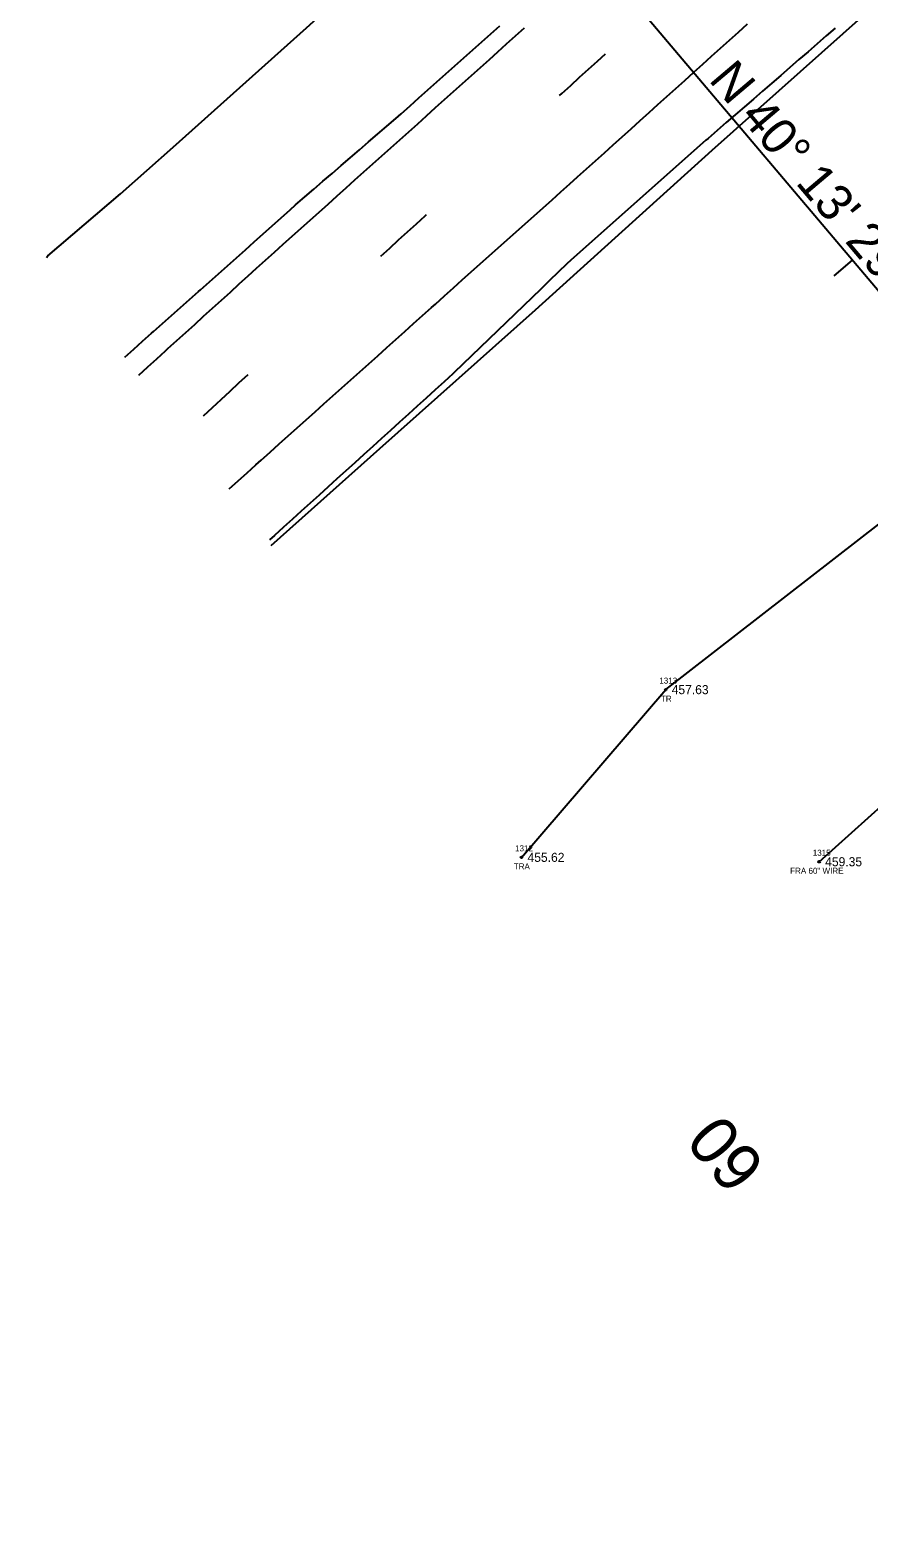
# Model space of a CAD drawing. Extents: x 1745838 to 1751416, y 649214 to 655806.
# Drawn here: x 1749097.1 to 1749236.5, y 651090.3 to 651340.9 of the extents above; entities that cross this region are included whole.
import ezdxf

# ---------------------------------------------------------------- set-up
doc = ezdxf.new("R2010")
doc.units = 0
for name, color, linetype in [('RD_EX_Fence_Other', 7, 'Continuous'), ('RD_EX_Fence_Other_txCode', 7, 'Continuous'), ('RD_EX_GuardRail', 7, 'Continuous'), ('RD_EX_Pavement_Markings', 7, 'Continuous'), ('RD_EX_Road', 7, 'Continuous'), ('RD_EX_TX_Fence_Other_ELEV', 7, 'Continuous'), ('RD_EX_TX_VEG_ELEV', 7, 'Continuous'), ('RD_EX_VEG', 7, 'Continuous'), ('RD_EX_VEG_txCode', 7, 'Continuous'), ('RD_HC_Cl', 7, 'Continuous'), ('RD_HC_Data', 7, 'Continuous'), ('RD_HC_Data_Tic', 7, 'Continuous'), ('RD_HC_TX_Sta50', 7, 'Continuous'), ('RD_SMD_Locator', 7, 'Continuous')]:
    doc.layers.add(name, color=color, linetype=linetype)

msp = doc.modelspace()

# ---------------------------------------------------------------- linework, layer by layer
at = {"layer": 'RD_EX_Fence_Other'}
msp.add_lwpolyline([(1749228.24, 651202.64), (1749249.97, 651222.14), (1749249.97, 651222.14), (1749291.03, 651176.48), (1749358.68, 651100.15), (1749424.34, 651025.98), (1749461.84, 650986.11), (1749495.25, 650947.39), (1749527.17, 650911.79), (1749559.6, 650874.95), (1749594.11, 650836.92), (1749630.2, 650798.28), (1749673.95, 650750.13)], dxfattribs=at)
at = {"layer": 'RD_EX_GuardRail'}
for points in [[(1749099.81, 651303.06), (1749100.06, 651303.34), (1749112.13, 651313.64), (1749120.86, 651321.43), (1749143.04, 651341.25), (1749171.53, 651367.1), (1749204, 651396.86), (1749238.69, 651429.68), (1749253.32, 651443.2)], [(1749137.14, 651255.22), (1749155.22, 651271.31), (1749181.09, 651294.35), (1749210.48, 651320.9), (1749272.24, 651375.99)]]:
    msp.add_lwpolyline(points, dxfattribs=at)
at = {"layer": 'RD_EX_Pavement_Markings'}
for points in [[(1749115.16, 651283.53), (1749116.64, 651284.87), (1749118.13, 651286.21), (1749119.61, 651287.56), (1749120.01, 651287.92), (1749121.49, 651289.26), (1749122.97, 651290.61), (1749124.45, 651291.95), (1749125.93, 651293.3), (1749127.41, 651294.64), (1749128.89, 651295.98), (1749130.38, 651297.33), (1749131.86, 651298.67), (1749133.34, 651300.02), (1749134.72, 651301.27), (1749136.21, 651302.6), (1749137.69, 651303.94), (1749139.18, 651305.27), (1749140.67, 651306.61), (1749142.16, 651307.95), (1749143.65, 651309.28), (1749145.14, 651310.62), (1749146.63, 651311.95), (1749148.12, 651313.29), (1749149.61, 651314.62), (1749151.09, 651315.96), (1749152.58, 651317.29), (1749154.07, 651318.63), (1749155.56, 651319.96), (1749157.05, 651321.3), (1749158.54, 651322.64), (1749160.03, 651323.97), (1749161.51, 651325.31), (1749163, 651326.64), (1749164.49, 651327.98), (1749165.98, 651329.31), (1749167.47, 651330.65), (1749168.96, 651331.98), (1749170.45, 651333.32), (1749171.94, 651334.66), (1749173.43, 651335.99), (1749174.81, 651337.23), (1749176.29, 651338.57), (1749177.78, 651339.9), (1749179.27, 651341.24)], [(1749130.17, 651264.62), (1749131.66, 651265.95), (1749133.15, 651267.29), (1749134.63, 651268.62), (1749135.51, 651269.41), (1749137, 651270.74), (1749138.49, 651272.07), (1749139.98, 651273.41), (1749141.47, 651274.74), (1749142.96, 651276.08), (1749144.45, 651277.41), (1749145.94, 651278.75), (1749147.43, 651280.08), (1749148.92, 651281.42), (1749150.41, 651282.75), (1749151.9, 651284.08), (1749153.39, 651285.42), (1749154.88, 651286.75), (1749156.37, 651288.09), (1749157.86, 651289.42), (1749159.35, 651290.76), (1749160.84, 651292.09), (1749162.33, 651293.42), (1749163.82, 651294.76), (1749164.46, 651295.33), (1749165.95, 651296.67), (1749167.44, 651298), (1749168.93, 651299.33), (1749170.42, 651300.66), (1749171.91, 651302), (1749173.41, 651303.33), (1749174.9, 651304.66), (1749176.39, 651306), (1749177.88, 651307.33), (1749179.37, 651308.66), (1749180.86, 651310), (1749182.35, 651311.33), (1749183.84, 651312.66), (1749185.33, 651313.99), (1749186.82, 651315.33), (1749188.08, 651316.45), (1749189.57, 651317.79), (1749191.05, 651319.13), (1749192.54, 651320.47), (1749194.02, 651321.8), (1749195.51, 651323.14), (1749197, 651324.48), (1749198.48, 651325.82), (1749199.97, 651327.16), (1749201.45, 651328.5), (1749202.94, 651329.84), (1749204.43, 651331.17), (1749205.91, 651332.51), (1749207.4, 651333.85), (1749208.88, 651335.19), (1749210.37, 651336.53), (1749211.86, 651337.87), (1749213.34, 651339.21), (1749214.83, 651340.54), (1749216.31, 651341.88)], [(1749185.08, 651330.01), (1749185.45, 651330.34), (1749186.94, 651331.68), (1749188.42, 651333.02), (1749189.9, 651334.36), (1749191.39, 651335.7), (1749192.71, 651336.9)], [(1749155.38, 651303.3), (1749156.86, 651304.64), (1749158.34, 651305.99), (1749159.82, 651307.33), (1749161.3, 651308.68), (1749162.78, 651310.02), (1749162.98, 651310.21)], [(1749125.92, 651276.77), (1749127.39, 651278.13), (1749128.86, 651279.49), (1749130.32, 651280.85), (1749131.79, 651282.21), (1749133.33, 651283.63)]]:
    msp.add_lwpolyline(points, dxfattribs=at)
at = {"layer": 'RD_EX_Road'}
for points in [[(1749112.81, 651286.49), (1749114.31, 651287.82), (1749115.8, 651289.15), (1749117.29, 651290.48), (1749117.62, 651290.77), (1749119.12, 651292.1), (1749120.61, 651293.43), (1749122.11, 651294.76), (1749123.6, 651296.09), (1749125.1, 651297.41), (1749125.41, 651297.69), (1749126.9, 651299.02), (1749128.39, 651300.36), (1749129.88, 651301.69), (1749131.37, 651303.02), (1749132.87, 651304.35), (1749134.36, 651305.68), (1749135.85, 651307.02), (1749137.34, 651308.35), (1749138.83, 651309.68), (1749140.33, 651311.01), (1749141.23, 651311.82), (1749142.74, 651313.13), (1749144.26, 651314.43), (1749145.77, 651315.74), (1749147.29, 651317.05), (1749148.8, 651318.35), (1749150.31, 651319.66), (1749151.83, 651320.97), (1749153.34, 651322.27), (1749154.86, 651323.58), (1749156.37, 651324.89), (1749157.88, 651326.19), (1749158.74, 651326.93), (1749160.24, 651328.26), (1749161.73, 651329.59), (1749163.22, 651330.92), (1749164.72, 651332.25), (1749166.21, 651333.58), (1749167.71, 651334.91), (1749169.2, 651336.24), (1749170.69, 651337.57), (1749172.19, 651338.9), (1749173.68, 651340.23), (1749175.17, 651341.56)], [(1749230.92, 651341.2), (1749229.41, 651339.89), (1749227.9, 651338.58), (1749226.39, 651337.27), (1749224.88, 651335.96), (1749223.37, 651334.65), (1749221.86, 651333.34), (1749220.35, 651332.03), (1749218.84, 651330.72), (1749217.32, 651329.41), (1749215.81, 651328.1), (1749214.3, 651326.79), (1749212.79, 651325.48), (1749211.28, 651324.17), (1749209.77, 651322.86), (1749209.42, 651322.55), (1749207.92, 651321.22), (1749206.43, 651319.89), (1749204.93, 651318.57), (1749203.44, 651317.24), (1749201.94, 651315.91), (1749200.45, 651314.58), (1749198.95, 651313.25), (1749197.46, 651311.93), (1749195.96, 651310.6), (1749194.46, 651309.27), (1749192.97, 651307.94), (1749191.48, 651306.61), (1749189.98, 651305.28), (1749188.49, 651303.95), (1749186.99, 651302.63), (1749186.28, 651302), (1749184.85, 651300.61), (1749183.41, 651299.22), (1749181.97, 651297.83), (1749180.53, 651296.44), (1749179.09, 651295.05), (1749177.65, 651293.66), (1749176.21, 651292.28), (1749174.78, 651290.89), (1749173.34, 651289.5), (1749171.9, 651288.11), (1749170.46, 651286.72), (1749169.02, 651285.33), (1749167.58, 651283.94), (1749167.37, 651283.73), (1749165.89, 651282.39), (1749164.4, 651281.05), (1749162.92, 651279.71), (1749161.44, 651278.36), (1749159.96, 651277.02), (1749158.47, 651275.68), (1749156.99, 651274.33), (1749155.51, 651272.99), (1749154.03, 651271.65), (1749152.54, 651270.31), (1749151.06, 651268.96), (1749149.58, 651267.62), (1749148.1, 651266.28), (1749146.61, 651264.94), (1749145.13, 651263.59), (1749143.65, 651262.25), (1749142.17, 651260.91), (1749140.69, 651259.57), (1749139.21, 651258.23), (1749137.72, 651256.88), (1749136.9, 651256.14)]]:
    msp.add_lwpolyline(points, dxfattribs=at)
at = {"layer": 'RD_EX_VEG'}
msp.add_lwpolyline([(1749178.77, 651203.37), (1749202.73, 651231.24), (1749238.66, 651259.14), (1749294.64, 651175.67), (1749358.68, 651100.15), (1749424.34, 651025.98), (1749461.84, 650986.11), (1749495.25, 650947.39), (1749527.17, 650911.79), (1749559.6, 650874.95), (1749594.11, 650836.92), (1749630.2, 650798.28), (1749696.62, 650725.69)], dxfattribs=at)
at = {"layer": 'RD_HC_Cl'}
msp.add_line((1749546.44, 650932.91), (1748908.1, 651687.62), dxfattribs=at)
at = {"layer": 'RD_HC_Data_Tic'}
msp.add_line((1749233.74, 651302.62), (1749230.68, 651300.04), dxfattribs=at)
at = {"layer": 'RD_SMD_Locator'}
for centre in [(1749202.73, 651231.24), (1749178.77, 651203.37), (1749228.24, 651202.64)]:
    msp.add_circle(centre, 0.15, dxfattribs=at)

# ---------------------------------------------------------------- texts
at = {"layer": 'RD_EX_Fence_Other_txCode'}
for s, p in [('1315', (1749227.18, 651203.64)), ('FRA 60" WIRE', (1749223.42, 651200.64))]:
    msp.add_text(s, height=1, dxfattribs=at).set_placement(p)
at = {"layer": 'RD_EX_TX_Fence_Other_ELEV'}
msp.add_text('459.35', height=1.5, dxfattribs=at).set_placement((1749229.24, 651201.89))
at = {"layer": 'RD_EX_TX_VEG_ELEV'}
for s, p in [('457.63', (1749203.73, 651230.49)), ('455.62', (1749179.77, 651202.62))]:
    msp.add_text(s, height=1.5, dxfattribs=at).set_placement(p)
at = {"layer": 'RD_EX_VEG_txCode'}
for s, p in [('1313', (1749201.67, 651232.24)), ('TR', (1749201.94, 651229.24)), ('1312', (1749177.7, 651204.37)), ('TRA', (1749177.48, 651201.37))]:
    msp.add_text(s, height=1, dxfattribs=at).set_placement(p)
at = {"layer": 'RD_HC_Data'}
msp.add_text('N 40%%d 13\' 29" W', height=6, rotation=310.2248, dxfattribs=at).set_placement((1749209.74, 651332.54))
at = {"layer": 'RD_HC_TX_Sta50'}
msp.add_text('60', height=8, rotation=130.2248, dxfattribs=at).set_placement((1749219.6, 651152.1))

doc.saveas('drawing.dxf')
